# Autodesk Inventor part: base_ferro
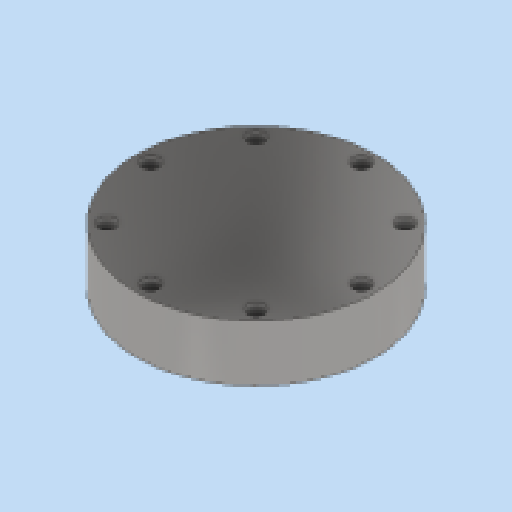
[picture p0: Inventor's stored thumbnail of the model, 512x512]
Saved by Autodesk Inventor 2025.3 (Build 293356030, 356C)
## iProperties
Created: 2026-01
Part Number: base_ferro
Material: Acciaio
Document SubType Name: Modeling
Designer: Ryzen5700u
Density: 7.85 g/cm^3
Appearance: Acciaio - Lucido
Mass: 7039.17 g
Surface Area: 726.938 cm^2
Volume: 896.709 cm^3
Author: Ryzen5700u
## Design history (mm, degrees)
sketch "Schizzo1"
  geometry: C1 r 85 at (0, 0); 1 further point
  constraints: 1 centre point, 1 coincident
  dimensions: "d0" = 170 diameter of C1
extrude "Estrusione1" new body sketch "Schizzo1" distance "d1" = 40; taper "d2" = 0 deg
sketch "Schizzo2"
  geometry: L1 (0, 0)-(0, -85); 1 further point
  constraints: 2 end point, 1 point on line, 1 vertical, 1 vertical alignment, 1 other
  dimensions: "d10" = 75 distance of L1.start point (0, -75)
hole "Foro1" sketch "Schizzo2" at (0, -75) diameter "d3" = 5.3; stored, may be unused: countersink angle "d7" = 90 deg, drill point angle "d9" = 118 deg; dims "d4" = 6, "d5" = 12, "d6" = 20, "d8" = 8
pattern_circular "Serie circolare1" dims angle "d12" = 360 deg
node "Solido1"
node "Linea chiusa proiettata1"
